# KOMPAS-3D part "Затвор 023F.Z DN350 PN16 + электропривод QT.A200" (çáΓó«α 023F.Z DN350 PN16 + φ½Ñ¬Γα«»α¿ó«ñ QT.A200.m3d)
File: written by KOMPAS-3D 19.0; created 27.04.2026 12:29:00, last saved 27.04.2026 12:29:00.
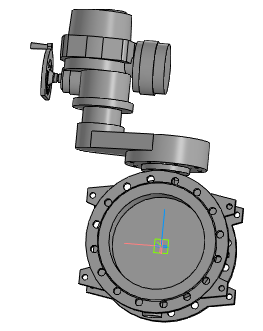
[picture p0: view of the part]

Document properties: Полное имя файла: Затвор 023F.Z DN350 PN16 + электропривод QT.A200.a3d

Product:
- Part/product: Затвор 023F.Z DN350 PN16 + электропривод QT.A200
    Масса: 356.872

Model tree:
1. Операция без истории:1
